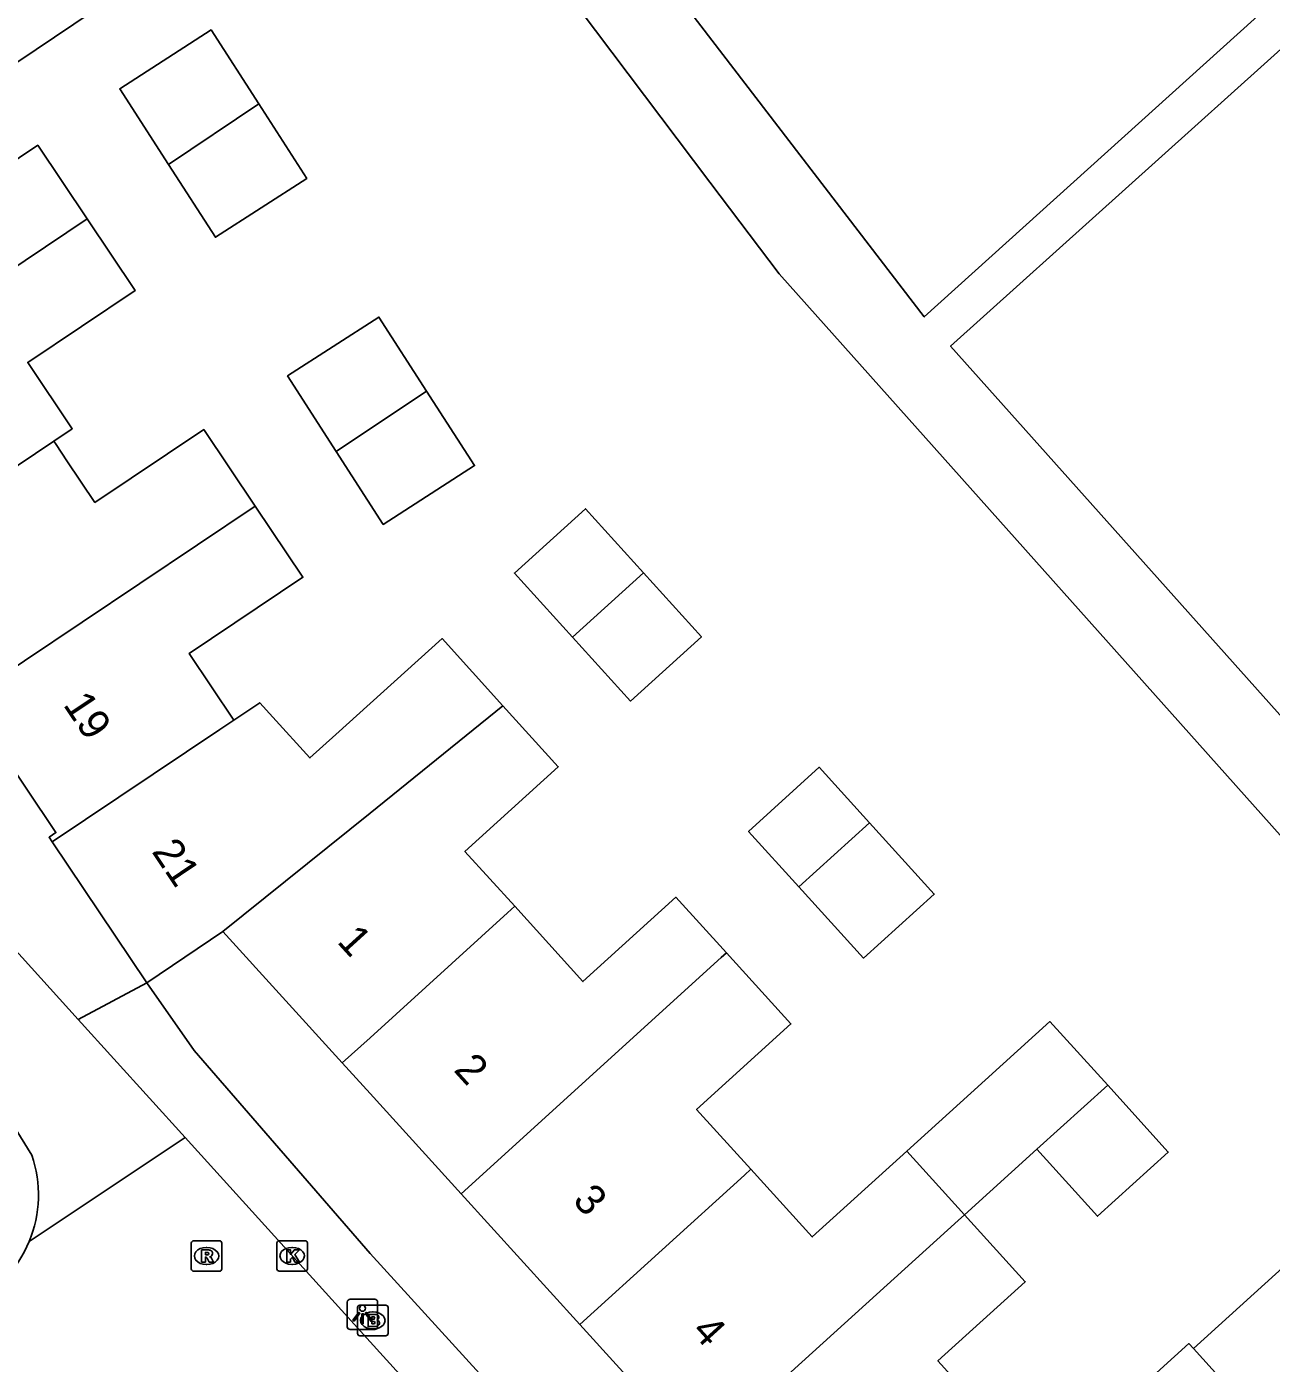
# Model space of a CAD drawing. Extents: x 158352 to 159489, y 383828 to 384597.
# Drawn here: x 158988.73 to 159029.58, y 384188.86 to 384232.74 of the extents above; entities that cross this region are included whole.
import ezdxf

# ---------------------------------------------------------------- set-up
doc = ezdxf.new("R2010")
doc.units = 0
for name, color, linetype in [('IMGEO_Brandkraan', 7, 'Continuous'), ('IMGEO_Kolk', 7, 'Continuous'), ('IMGEO_Lichtpunt', 7, 'Continuous'), ('IMGEO_Pand', 7, 'Continuous'), ('IMGEO_Pand_nummerreeks', 7, 'Continuous'), ('IMGEO_Rijbaan_lokaal_open', 7, 'Continuous'), ('IMGEO_Rioolput', 7, 'Continuous'), ('IMGEO_Voetpad_open', 7, 'Continuous')]:
    doc.layers.add(name, color=color, linetype=linetype)

msp = doc.modelspace()

# ---------------------------------------------------------------- linework, layer by layer
at = {"layer": 'IMGEO_Brandkraan'}
for p, q in [((158999.589, 384189.836), (158999.589, 384190.688)), ((158999.664, 384190.762), (159000.516, 384190.762)), ((159000.077, 384190.542), (159000.102, 384190.542)), ((159000.59, 384190.688), (159000.59, 384189.836)), ((159000.1, 384189.982), (159000.075, 384189.982)), ((159000.516, 384189.762), (158999.664, 384189.762))]:
    msp.add_line(p, q, dxfattribs=at)
for points in [[(158999.589, 384189.836), (158999.589, 384190.688)], [(158999.664, 384190.762), (159000.516, 384190.762)], [(158999.937, 384190.462), (158999.937, 384190.062), (159000.15, 384190.062)], [(159000.168, 384190.462), (158999.937, 384190.462)], [(159000.59, 384190.688), (159000.59, 384189.836)], [(159000.116, 384190.381), (159000.062, 384190.381), (159000.062, 384190.305)], [(159000.062, 384190.305), (159000.115, 384190.305)], [(159000.124, 384190.229), (159000.062, 384190.229), (159000.062, 384190.148)], [(159000.062, 384190.148), (159000.124, 384190.148)], [(159000.516, 384189.762), (158999.664, 384189.762)]]:
    msp.add_lwpolyline(points, dxfattribs=at)
for centre, radius, start, end in [((158999.666, 384190.686), 0.0765, 91.552, 178.448), ((158999.666, 384190.686), 0.0765, 91.552, 178.448), ((159000.172, 384190.317), 0.145, 59.4692, 91.5367), ((159000.197, 384190.364), 0.0922, 285.5137, 58.1501), ((159000.514, 384190.686), 0.0765, 1.552, 88.448), ((159000.514, 384190.686), 0.0765, 1.552, 88.448), ((159000.117, 384190.343), 0.0379, 267.8285, 90.9355), ((159000.125, 384190.188), 0.0404, 269.8759, 90.5077), ((159000.156, 384190.313), 0.251, 268.6676, 293.5347), ((159000.202, 384190.172), 0.105, 301.3115, 78.989), ((158999.666, 384189.838), 0.0765, 181.552, 268.448), ((158999.666, 384189.838), 0.0765, 181.552, 268.448), ((159000.514, 384189.838), 0.0765, 271.552, 358.448), ((159000.514, 384189.838), 0.0765, 271.552, 358.448)]:
    msp.add_arc(centre, radius, start, end, dxfattribs=at)
for centre, major_axis, ratio, start_param, end_param in [((159000.076, 384190.262), (-0.387, 0.002), 0.722429, 4.712389, 7.853982), ((159000.101, 384190.262), (-0.39, 0.002), 0.717154, 1.570796, 4.712389)]:
    msp.add_ellipse(centre, major_axis=major_axis, ratio=ratio, start_param=start_param, end_param=end_param, dxfattribs=at)
at = {"layer": 'IMGEO_Kolk'}
for p, q in [((158996.943, 384191.955), (158996.943, 384192.807)), ((158997.018, 384192.881), (158997.87, 384192.881)), ((158997.431, 384192.661), (158997.456, 384192.661)), ((158997.944, 384192.807), (158997.944, 384191.955)), ((158997.87, 384191.881), (158997.018, 384191.881)), ((158997.454, 384192.101), (158997.429, 384192.101))]:
    msp.add_line(p, q, dxfattribs=at)
for points in [[(158996.943, 384191.955), (158996.943, 384192.807)], [(158997.018, 384192.881), (158997.87, 384192.881)], [(158997.944, 384192.807), (158997.944, 384191.955)], [(158997.264, 384192.581), (158997.387, 384192.581), (158997.387, 384192.43), (158997.517, 384192.581), (158997.681, 384192.581), (158997.535, 384192.43), (158997.688, 384192.181), (158997.536, 384192.181), (158997.451, 384192.345), (158997.387, 384192.278), (158997.387, 384192.181), (158997.264, 384192.181), (158997.264, 384192.581)], [(158997.87, 384191.881), (158997.018, 384191.881)]]:
    msp.add_lwpolyline(points, dxfattribs=at)
for centre, start, end in [((158997.02, 384192.805), 91.552, 178.448), ((158997.02, 384192.805), 91.552, 178.448), ((158997.868, 384192.805), 1.552, 88.448), ((158997.868, 384192.805), 1.552, 88.448), ((158997.02, 384191.957), 181.552, 268.448), ((158997.02, 384191.957), 181.552, 268.448), ((158997.868, 384191.957), 271.552, 358.448), ((158997.868, 384191.957), 271.552, 358.448)]:
    msp.add_arc(centre, 0.0765, start, end, dxfattribs=at)
for centre, major_axis, ratio, start_param, end_param in [((158997.43, 384192.381), (-0.387, 0.002), 0.722429, 4.712389, 7.853982), ((158997.455, 384192.381), (-0.39, 0.002), 0.717154, 1.570796, 4.712389)]:
    msp.add_ellipse(centre, major_axis=major_axis, ratio=ratio, start_param=start_param, end_param=end_param, dxfattribs=at)
at = {"layer": 'IMGEO_Lichtpunt'}
for p, q in [((158999.253, 384190.865), (158999.253, 384190.058)), ((158999.253, 384190.865), (158999.253, 384190.058)), ((159000.155, 384190.96), (158999.347, 384190.96)), ((159000.155, 384190.96), (158999.347, 384190.96)), ((159000.249, 384190.058), (159000.249, 384190.865)), ((159000.249, 384190.058), (159000.249, 384190.865)), ((158999.347, 384189.964), (159000.155, 384189.964)), ((158999.347, 384189.964), (159000.155, 384189.964))]:
    msp.add_line(p, q, dxfattribs=at)
for points in [[(158999.627, 384190.529), (158999.666, 384190.501), (158999.478, 384190.239), (158999.44, 384190.266), (158999.627, 384190.529)], [(158999.729, 384190.481), (158999.776, 384190.481), (158999.776, 384190.159), (158999.729, 384190.159), (158999.729, 384190.481)], [(158999.839, 384190.501), (158999.877, 384190.528), (159000.064, 384190.266), (159000.025, 384190.238), (158999.839, 384190.501)]]:
    msp.add_lwpolyline(points, dxfattribs=at)
msp.add_circle((158999.752, 384190.663), 0.0994, dxfattribs=at)
for centre, start, end in [((158999.347, 384190.865), 90, 180), ((158999.347, 384190.865), 90, 180), ((159000.155, 384190.865), 0, 90), ((159000.155, 384190.865), 0, 90), ((158999.347, 384190.058), 180, 270), ((158999.347, 384190.058), 180, 270), ((159000.155, 384190.058), 270, 0), ((159000.155, 384190.058), 270, 360)]:
    msp.add_arc(centre, 0.0946, start, end, dxfattribs=at)
at = {"layer": 'IMGEO_Pand'}
for points in [[(158996.345, 384230.203), (158994.783, 384232.63), (158991.783, 384230.699), (158993.382, 384228.215)], [(158996.345, 384230.203), (158993.382, 384228.215)], [(158993.382, 384228.215), (158994.923, 384225.823), (158997.922, 384227.754), (158996.345, 384230.203)], [(158990.717, 384226.427), (158989.094, 384228.845), (158985.511, 384226.44), (158984.024, 384228.622)], [(158990.717, 384226.427), (158981.197, 384220.039)], [(158989.619, 384219.13), (158990.223, 384219.535), (158988.762, 384221.713), (158992.291, 384224.081), (158990.717, 384226.427)], [(159001.853, 384220.776), (159000.291, 384223.203), (158997.291, 384221.272), (158998.89, 384218.788)], [(158998.89, 384218.788), (159000.431, 384216.396), (159003.43, 384218.327), (159001.853, 384220.776)], [(158998.89, 384218.788), (159001.853, 384220.776)], [(158996.225, 384217), (158994.54, 384219.511), (158990.97, 384217.116), (158990.05, 384218.487), (158989.694, 384219.018), (158989.619, 384219.13)], [(158983.721, 384215.172), (158989.619, 384219.13)], [(158996.225, 384217), (158986.757, 384210.647)], [(158995.525, 384209.968), (158994.058, 384212.155), (158997.794, 384214.662), (158996.225, 384217)], [(159008.972, 384214.806), (159007.071, 384216.909), (159004.738, 384214.798), (159006.643, 384212.696)], [(159006.643, 384212.696), (159008.549, 384210.594), (159010.874, 384212.704), (159008.972, 384214.806)], [(159006.643, 384212.696), (159008.972, 384214.806)], [(159004.363, 384210.444), (159002.362, 384212.65), (159000, 384210.514), (158998.878, 384209.5), (158998.025, 384208.729), (158996.806, 384210.073), (158996.38, 384210.542), (158995.525, 384209.968)], [(158989.567, 384205.97), (158989.462, 384206.127), (158989.688, 384206.279), (158986.757, 384210.647)], [(159004.363, 384210.444), (159000, 384206.921), (158995.172, 384203.027)], [(159004.747, 384203.86), (159003.112, 384205.663), (159006.177, 384208.443), (159004.363, 384210.444)], [(158989.567, 384205.97), (158995.074, 384209.665), (158995.525, 384209.968)], [(159016.395, 384206.604), (159014.746, 384208.422), (159012.426, 384206.318), (159014.076, 384204.497)], [(159014.076, 384204.497), (159016.197, 384202.159), (159018.518, 384204.262), (159016.395, 384206.604)], [(159014.076, 384204.497), (159016.395, 384206.604)], [(158992.67, 384201.347), (158989.567, 384205.97)], [(159011.695, 384202.333), (159010.042, 384204.157), (159006.988, 384201.388), (159004.747, 384203.86)], [(159004.747, 384203.86), (159004.508, 384203.643), (159000, 384199.546), (158999.088, 384198.716)], [(158995.172, 384203.027), (158992.67, 384201.347)], [(158999.088, 384198.716), (158995.172, 384203.027)], [(159011.695, 384202.333), (159011.523, 384202.177), (159002.989, 384194.422)], [(159012.5, 384195.225), (159010.718, 384197.191), (159013.813, 384199.997), (159011.695, 384202.333)], [(159024.211, 384197.983), (159022.314, 384200.075), (159019.721, 384197.725), (159017.618, 384195.819)], [(158999.088, 384198.716), (159000, 384197.712), (159002.989, 384194.422)], [(159021.889, 384195.88), (159023.88, 384193.685), (159026.2, 384195.789), (159024.211, 384197.983)], [(159021.889, 384195.88), (159024.211, 384197.983)], [(159017.618, 384195.819), (159014.513, 384193.005), (159012.5, 384195.225)], [(159019.512, 384193.729), (159017.618, 384195.819)], [(159019.512, 384193.729), (159021.889, 384195.88)], [(159006.89, 384190.127), (159012.292, 384195.036), (159012.5, 384195.225)], [(159002.989, 384194.422), (159006.89, 384190.127)], [(159028.769, 384187.42), (159033.802, 384191.987), (159032.058, 384193.909), (159027.026, 384189.342)], [(159019.512, 384193.729), (159019.309, 384193.545), (159010.79, 384185.833)], [(159017.433, 384184.419), (159020.34, 384187.055), (159018.639, 384188.932), (159021.505, 384191.531), (159019.512, 384193.729)], [(159010.79, 384185.833), (159006.89, 384190.127)], [(159027.026, 384189.342), (159026.879, 384189.504), (159024.287, 384187.152), (159022.337, 384185.384)], [(159028.769, 384187.42), (159027.026, 384189.342)]]:
    msp.add_lwpolyline(points, dxfattribs=at)
at = {"layer": 'IMGEO_Rijbaan_lokaal_open'}
for points in [[(158983.668, 384207.891), (158984.272, 384207.041), (158984.897, 384206.251), (158990.424, 384200.141)], [(158990.424, 384200.141), (158993.927, 384196.269)], [(158988.153, 384196.891), (158988.895, 384195.685)], [(158993.927, 384196.269), (158988.811, 384192.855)], [(159021.065, 384166.299), (159006.524, 384182.375), (159000, 384189.555), (158993.927, 384196.269)]]:
    msp.add_lwpolyline(points, dxfattribs=at)
for centre, radius, start, end in [((158985.178, 384194.379), 3.94, 337.2411, 19.3586), ((158985.182, 384194.375), 3.935, 295.1026, 337.273)]:
    msp.add_arc(centre, radius, start, end, dxfattribs=at)
at = {"layer": 'IMGEO_Rioolput'}
for p, q in [((158994.133, 384191.952), (158994.133, 384192.804)), ((158994.208, 384192.878), (158995.06, 384192.878)), ((158994.621, 384192.658), (158994.646, 384192.658)), ((158995.134, 384192.804), (158995.134, 384191.952)), ((158995.06, 384191.878), (158994.208, 384191.878)), ((158994.644, 384192.098), (158994.619, 384192.098))]:
    msp.add_line(p, q, dxfattribs=at)
for points in [[(158994.133, 384191.952), (158994.133, 384192.804)], [(158994.208, 384192.878), (158995.06, 384192.878)], [(158995.134, 384192.804), (158995.134, 384191.952)], [(158994.722, 384192.576), (158994.47, 384192.578), (158994.47, 384192.178)], [(158994.47, 384192.178), (158994.594, 384192.178), (158994.594, 384192.34), (158994.605, 384192.34)], [(158994.648, 384192.497), (158994.594, 384192.497), (158994.594, 384192.416)], [(158994.594, 384192.416), (158994.646, 384192.416)], [(158994.652, 384192.311), (158994.723, 384192.178), (158994.863, 384192.178), (158994.798, 384192.304)], [(158995.06, 384191.878), (158994.208, 384191.878)]]:
    msp.add_lwpolyline(points, dxfattribs=at)
for centre, radius, start, end in [((158994.21, 384192.802), 0.0765, 91.552, 178.448), ((158994.21, 384192.802), 0.0765, 91.552, 178.448), ((158995.058, 384192.802), 0.0765, 1.552, 88.448), ((158995.058, 384192.802), 0.0765, 1.552, 88.448), ((158994.604, 384192.287), 0.0533, 26.0293, 88.6989), ((158994.63, 384192.605), 0.19, 274.7715, 282.9687), ((158994.654, 384192.401), 0.0964, 77.0061, 93.1865), ((158994.668, 384192.458), 0.0378, 276.6634, 79.6772), ((158994.721, 384192.466), 0.109, 350.3612, 89.416), ((158994.719, 384192.466), 0.112, 277.5842, 350.9817), ((158994.703, 384192.251), 0.108, 29.5134, 73.7905), ((158994.21, 384191.954), 0.0765, 181.552, 268.448), ((158994.21, 384191.954), 0.0765, 181.552, 268.448), ((158995.058, 384191.954), 0.0765, 271.552, 358.448), ((158995.058, 384191.954), 0.0765, 271.552, 358.448)]:
    msp.add_arc(centre, radius, start, end, dxfattribs=at)
for centre, major_axis, ratio, start_param, end_param in [((158994.62, 384192.378), (-0.387, 0.002), 0.722429, 4.712389, 7.853982), ((158994.645, 384192.378), (-0.39, 0.002), 0.717154, 1.570796, 4.712389)]:
    msp.add_ellipse(centre, major_axis=major_axis, ratio=ratio, start_param=start_param, end_param=end_param, dxfattribs=at)
at = {"layer": 'IMGEO_Voetpad_open'}
for points in [[(159029.577, 384233.483), (159018.193, 384223.211), (159002.801, 384243.272), (159012.653, 384252.17)], [(158984.024, 384228.622), (159001.534, 384240.404), (159011.157, 384227.628), (159013.427, 384224.622), (159030.506, 384205.481), (159038.831, 384196.151)], [(159047.545, 384214.039), (159035.907, 384203.368), (159019.056, 384222.244), (159030.537, 384232.575)], [(158990.424, 384200.141), (158992.67, 384201.347)], [(159008.184, 384183.474), (159000, 384192.464), (158994.231, 384199.124), (158992.67, 384201.347)]]:
    msp.add_lwpolyline(points, dxfattribs=at)

# ---------------------------------------------------------------- texts
at = {"layer": 'IMGEO_Pand_nummerreeks'}
for s, rotation, p in [('19', 303.8387, (158989.907, 384210.478)), ('21', 303.8673, (158992.814, 384205.655)), ('1', 312.2512, (158998.887, 384202.685)), ('2', 312.2492, (159002.717, 384198.469)), ('3', 312.2492, (159006.618, 384194.174)), ('4', 312.2497, (159010.52, 384189.879))]:
    msp.add_text(s, height=1, rotation=rotation, dxfattribs=at).set_placement(p)

doc.saveas('drawing.dxf')
